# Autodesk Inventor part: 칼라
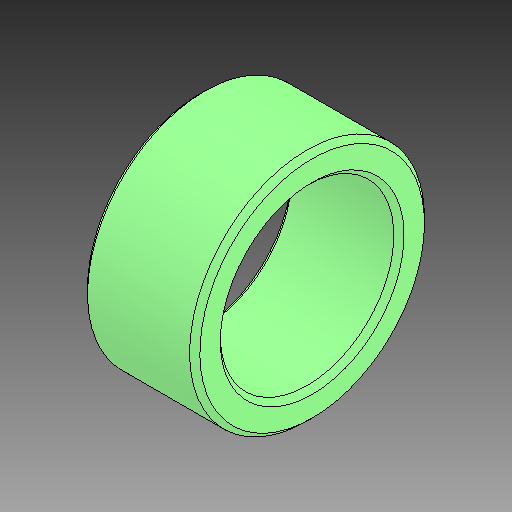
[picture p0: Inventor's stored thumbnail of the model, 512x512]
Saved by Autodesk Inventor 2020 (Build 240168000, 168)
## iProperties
Created: 2025-03
Part Number: 칼라
Material: 일반
Document SubType Name: Modeling
Designer: CA01
Density: 1 g/cm^3
Appearance: 기본값
Author: jhkim
Sending System: Autodesk Inventor 2025
Preprocessor: ST-DEVELOPER v20
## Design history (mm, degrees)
feature "솔리드1"
node "솔리드2"
